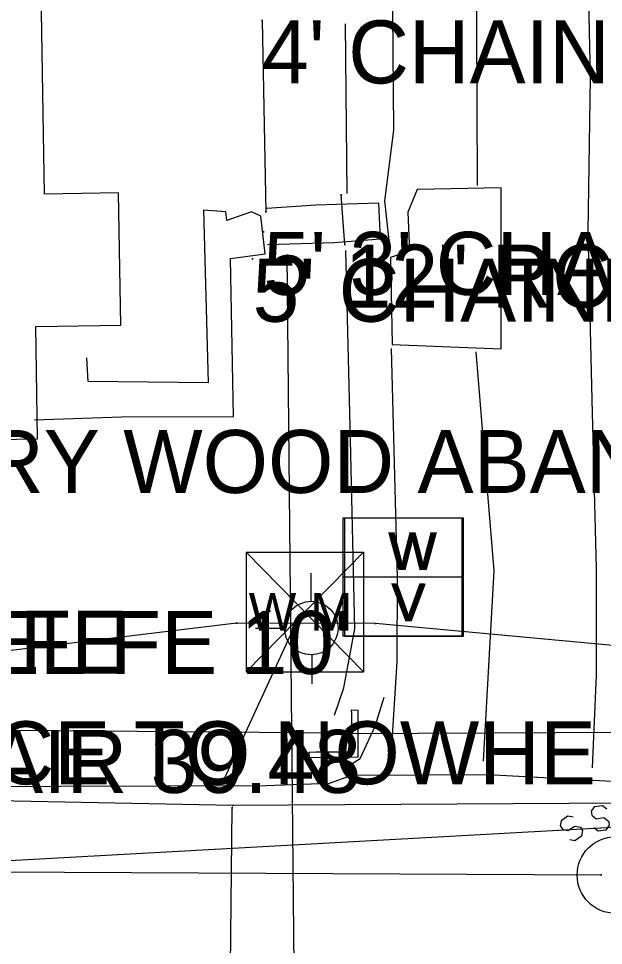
# Model space of a CAD drawing. Extents: x 1304270 to 1306561, y 1876019 to 1876752.
# Drawn here: x 1305299.9 to 1305346.4, y 1876408.6 to 1876482.3 of the extents above; entities that cross this region are included whole.
import ezdxf

# ---------------------------------------------------------------- set-up
doc = ezdxf.new("R2010")
doc.units = 0
for name, color, linetype in [('Default', 7, 'Continuous'), ('S_BUILDING', 7, 'Continuous'), ('S_CROSS_DRAIN', 7, 'Continuous'), ('S_DITCHLINE', 7, 'Continuous'), ('S_DRG_PT_SYM', 7, 'Continuous'), ('S_EDGE_CONCRETE', 7, 'Continuous'), ('S_EDGE_PAVEMENT', 7, 'Continuous'), ('S_FENCE', 7, 'Continuous'), ('S_FENCE_ANNOT', 7, 'Continuous'), ('S_FIBER_OPTIC_CABLE', 7, 'Continuous'), ('S_GAS_UTILITIES', 7, 'Continuous'), ('S_GATE_ANNOT', 7, 'Continuous'), ('S_HEADWALL', 7, 'Continuous'), ('S_MSC_PT_SYM', 7, 'Continuous'), ('S_PAVEMENT_CROWN', 7, 'Continuous'), ('S_SANITARY_SEWER', 7, 'Continuous'), ('S_SIDE_DRAIN', 7, 'Continuous'), ('S_SIDE_DRAIN_ANNOT', 7, 'Continuous'), ('S_SIDEWALK', 7, 'Continuous'), ('S_SURVEY_TEXT_ANNOT', 7, 'Continuous'), ('S_UTILITY_POLE', 7, 'Continuous'), ('S_UTL_PT_SYM', 7, 'Continuous'), ('S_WATER_UTILITIES', 7, 'Continuous')]:
    doc.layers.add(name, color=color, linetype=linetype)

msp = doc.modelspace()

# ---------------------------------------------------------------- linework, layer by layer
at = {"layer": 'Default'}
msp.add_line((1304873.941, 1876392.06), (1305473.534, 1876424.943), dxfattribs=at)
at = {"layer": 'S_BUILDING'}
msp.add_lwpolyline([(1305280.999, 1876496.939), (1305281.797, 1876448.543), (1305301.418, 1876448.867), (1305301.271, 1876457.78), (1305308.025, 1876457.891), (1305307.852, 1876468.402), (1305301.975, 1876468.305), (1305301.498, 1876497.277)], close=True, dxfattribs=at)
at = {"layer": 'S_CROSS_DRAIN'}
msp.add_line((1305350.386, 1876425.555), (1305326.154, 1876425.439), dxfattribs=at)
at = {"layer": 'S_DITCHLINE'}
for points in [[(1305326.03, 1876468.356), (1305325.896, 1876481.83)], [(1305325.015, 1876426.92), (1305325.765, 1876429.079), (1305326.635, 1876433.767), (1305326.286, 1876448.795), (1305325.938, 1876463.822)], [(1305247.208, 1876425.534), (1305267.671, 1876425.797), (1305283.635, 1876425.755), (1305299.6, 1876425.713), (1305312.565, 1876425.609), (1305325.53, 1876425.505)]]:
    msp.add_lwpolyline(points, dxfattribs=at)
at = {"layer": 'S_DRG_PT_SYM'}
for points in [[(1305325.565, 1876468.262), (1305325.565, 1876468.312), (1305325.565, 1876468.262), (1305325.515, 1876468.262), (1305325.565, 1876468.262), (1305325.565, 1876468.212), (1305325.565, 1876468.262), (1305325.615, 1876468.262)], [(1305325.836, 1876464.292), (1305325.836, 1876464.342), (1305325.836, 1876464.292), (1305325.786, 1876464.292), (1305325.836, 1876464.292), (1305325.836, 1876464.242), (1305325.836, 1876464.292), (1305325.886, 1876464.292)], [(1305326.154, 1876425.439), (1305326.154, 1876425.489), (1305326.154, 1876425.439), (1305326.104, 1876425.439), (1305326.154, 1876425.439), (1305326.154, 1876425.389), (1305326.154, 1876425.439), (1305326.204, 1876425.439)]]:
    msp.add_lwpolyline(points, dxfattribs=at)
at = {"layer": 'S_EDGE_CONCRETE'}
msp.add_lwpolyline([(1305329.608, 1876456.359), (1305338.28, 1876456.008), (1305338.273, 1876468.819), (1305331.607, 1876468.685), (1305330.863, 1876466.885), (1305330.981, 1876463.768), (1305329.472, 1876463.283)], close=True, dxfattribs=at)
at = {"layer": 'S_EDGE_PAVEMENT'}
for points in [[(1305329.455, 1876463.889), (1305329.018, 1876467.771), (1305329.753, 1876473.393), (1305329.675, 1876482.774), (1305329.429, 1876494.438), (1305330.166, 1876496.055), (1305329.938, 1876509.82)], [(1305345.542, 1876422.727), (1305345.856, 1876430.097), (1305345.86, 1876438.578), (1305345.525, 1876451.96), (1305345.191, 1876465.343), (1305345.392, 1876477.545), (1305345.052, 1876492.413), (1305344.713, 1876507.282)], [(1305329.473, 1876422.797), (1305330.003, 1876431.14), (1305330.022, 1876437.816), (1305329.567, 1876456.036)], [(1305325.882, 1876422.728), (1305327.054, 1876423.478), (1305328.271, 1876426.031), (1305328.967, 1876428.336)], [(1305129.363, 1876422.241), (1305153.047, 1876421.961), (1305176.731, 1876421.682), (1305192.781, 1876421.819), (1305208.83, 1876421.956), (1305222.689, 1876422.089), (1305236.664, 1876421.776), (1305244.109, 1876421.463), (1305257.339, 1876421.298), (1305270.568, 1876421.134), (1305295.068, 1876421.237), (1305319.567, 1876421.34), (1305324.623, 1876421.519), (1305326.394, 1876422.138), (1305337.227, 1876422.202), (1305349.547, 1876421.533), (1305351.837, 1876421.087), (1305367.555, 1876421.039), (1305383.273, 1876420.992)]]:
    msp.add_lwpolyline(points, dxfattribs=at)
at = {"layer": 'S_FENCE'}
msp.add_line((1305319.262, 1876482.101), (1305319.557, 1876466.887), dxfattribs=at)
msp.add_lwpolyline([(1305319.262, 1876482.101), (1305319.557, 1876466.887)], dxfattribs=at)
msp.add_lwpolyline([(1305319.262, 1876482.101), (1305319.557, 1876466.887)], dxfattribs=at)
at = {"layer": 'S_FIBER_OPTIC_CABLE'}
for p, q in [((1305317.236, 1876434.23), (1305297.346, 1876431.803)), ((1305328.281, 1876434.187), (1305317.236, 1876434.23)), ((1305347.146, 1876432.44), (1305328.281, 1876434.187))]:
    msp.add_line(p, q, dxfattribs=at)
at = {"layer": 'S_GAS_UTILITIES'}
msp.add_line((1305321.239, 1876463.459), (1305322.005, 1876385.242), dxfattribs=at)
at = {"layer": 'S_HEADWALL'}
msp.add_lwpolyline([(1305326.885, 1876427.325), (1305326.894, 1876427.104), (1305326.876, 1876423.577), (1305323.169, 1876423.523), (1305323.036, 1876423.486), (1305323.005, 1876423.99), (1305323.573, 1876424.004), (1305326.398, 1876424.002), (1305326.395, 1876427.036), (1305326.368, 1876427.348)], close=True, dxfattribs=at)
at = {"layer": 'S_MSC_PT_SYM'}
for points in [[(1305319.262, 1876482.101), (1305319.262, 1876482.151), (1305319.262, 1876482.101), (1305319.212, 1876482.101), (1305319.262, 1876482.101), (1305319.262, 1876482.051), (1305319.262, 1876482.101), (1305319.312, 1876482.101)], [(1305319.557, 1876466.887), (1305319.557, 1876466.937), (1305319.557, 1876466.887), (1305319.507, 1876466.887), (1305319.557, 1876466.887), (1305319.557, 1876466.837), (1305319.557, 1876466.887), (1305319.607, 1876466.887)], [(1305319.368, 1876465.305), (1305319.368, 1876465.355), (1305319.368, 1876465.305), (1305319.318, 1876465.305), (1305319.368, 1876465.305), (1305319.368, 1876465.255), (1305319.368, 1876465.305), (1305319.418, 1876465.305)], [(1305318.506, 1876463.169), (1305318.506, 1876463.219), (1305318.506, 1876463.169), (1305318.456, 1876463.169), (1305318.506, 1876463.169), (1305318.506, 1876463.119), (1305318.506, 1876463.169), (1305318.556, 1876463.169)], [(1305319.885, 1876435.182), (1305319.885, 1876435.232), (1305319.885, 1876435.182), (1305319.835, 1876435.182), (1305319.885, 1876435.182), (1305319.885, 1876435.132), (1305319.885, 1876435.182), (1305319.935, 1876435.182)]]:
    msp.add_lwpolyline(points, dxfattribs=at)
at = {"layer": 'S_PAVEMENT_CROWN'}
for points in [[(1305336.405, 1876469.001), (1305336.307, 1876488.339), (1305336.209, 1876507.677)], [(1305336.886, 1876423.262), (1305337.727, 1876438.394), (1305336.28, 1876455.776)]]:
    msp.add_lwpolyline(points, dxfattribs=at)
at = {"layer": 'S_SANITARY_SEWER'}
for p, q in [((1305343.042, 1876418.517), (1305342.964, 1876418.13)), ((1305343.584, 1876418.905), (1305343.042, 1876418.517)), ((1305344.011, 1876418.827), (1305343.584, 1876418.905)), ((1305342.964, 1876418.13), (1305343.158, 1876417.859)), ((1305343.158, 1876417.859), (1305343.584, 1876417.742)), ((1305343.584, 1876417.742), (1305344.127, 1876418.091)), ((1305344.127, 1876418.091), (1305344.592, 1876418.014)), ((1305344.592, 1876418.014), (1305344.747, 1876417.742)), ((1305344.747, 1876417.742), (1305344.669, 1876417.316)), ((1305344.127, 1876416.929), (1305343.739, 1876417.006)), ((1305344.669, 1876417.316), (1305344.127, 1876416.929)), ((1304983.663, 1876415.964), (1305346.234, 1876414.239))]:
    msp.add_line(p, q, dxfattribs=at)
msp.add_lwpolyline([(1305346.684, 1876419.447), (1305346.336, 1876419.719), (1305345.677, 1876419.641), (1305345.444, 1876419.292), (1305345.483, 1876418.982), (1305345.832, 1876418.672), (1305346.452, 1876418.789), (1305346.839, 1876418.479), (1305346.878, 1876418.169), (1305346.607, 1876417.781), (1305345.987, 1876417.704), (1305345.638, 1876417.975)], dxfattribs=at)
msp.add_circle((1305347.369, 1876414.214), 3.048, dxfattribs=at)
at = {"layer": 'S_SIDE_DRAIN'}
msp.add_line((1305325.836, 1876464.292), (1305325.565, 1876468.262), dxfattribs=at)
at = {"layer": 'S_SIDEWALK'}
for points in [[(1305301.168, 1876450.369), (1305308.091, 1876450.611), (1305316.982, 1876450.648), (1305316.766, 1876463.197), (1305319.523, 1876463.563), (1305319.171, 1876466.545), (1305318.438, 1876466.9), (1305316.469, 1876466.198), (1305316.385, 1876466.898), (1305314.621, 1876467.03), (1305314.969, 1876453.322), (1305305.43, 1876453.421), (1305305.338, 1876455.289)], [(1305319.692, 1876464.309), (1305324.992, 1876464.471), (1305328.682, 1876464.759), (1305328.56, 1876467.592), (1305323.538, 1876467.417), (1305319.652, 1876467.17)]]:
    msp.add_lwpolyline(points, dxfattribs=at)
at = {"layer": 'S_UTILITY_POLE'}
for p, q in [((1305323.174, 1876435.945), (1305323.174, 1876438.193)), ((1305321.082, 1876433.814), (1305318.757, 1876433.814)), ((1305323.252, 1876429.397), (1305323.252, 1876431.722))]:
    msp.add_line(p, q, dxfattribs=at)
msp.add_circle((1305323.177, 1876433.835), 2.128, dxfattribs=at)
at = {"layer": 'S_UTL_PT_SYM'}
for points in [[(1305321.239, 1876463.459), (1305321.239, 1876463.509), (1305321.239, 1876463.459), (1305321.189, 1876463.459), (1305321.239, 1876463.459), (1305321.239, 1876463.409), (1305321.239, 1876463.459), (1305321.289, 1876463.459)], [(1305317.236, 1876434.23), (1305317.236, 1876434.28), (1305317.236, 1876434.23), (1305317.186, 1876434.23), (1305317.236, 1876434.23), (1305317.236, 1876434.18), (1305317.236, 1876434.23), (1305317.286, 1876434.23)], [(1305321.961, 1876434.236), (1305321.961, 1876434.286), (1305321.961, 1876434.236), (1305321.91, 1876434.236), (1305321.961, 1876434.236), (1305321.961, 1876434.186), (1305321.961, 1876434.236), (1305322.011, 1876434.236)], [(1305328.281, 1876434.187), (1305328.281, 1876434.237), (1305328.281, 1876434.187), (1305328.231, 1876434.187), (1305328.281, 1876434.187), (1305328.281, 1876434.137), (1305328.281, 1876434.187), (1305328.331, 1876434.187)], [(1305316.117, 1876421.579), (1305316.117, 1876421.629), (1305316.117, 1876421.579), (1305316.067, 1876421.579), (1305316.117, 1876421.579), (1305316.117, 1876421.529), (1305316.117, 1876421.579), (1305316.167, 1876421.579)], [(1305316.892, 1876419.562), (1305316.892, 1876419.612), (1305316.892, 1876419.562), (1305316.842, 1876419.562), (1305316.892, 1876419.562), (1305316.892, 1876419.512), (1305316.892, 1876419.562), (1305316.942, 1876419.562)], [(1305316.936, 1876419.741), (1305316.936, 1876419.791), (1305316.936, 1876419.741), (1305316.886, 1876419.741), (1305316.936, 1876419.741), (1305316.936, 1876419.691), (1305316.936, 1876419.741), (1305316.986, 1876419.741)], [(1305346.234, 1876414.239), (1305346.234, 1876414.289), (1305346.234, 1876414.239), (1305346.184, 1876414.239), (1305346.234, 1876414.239), (1305346.234, 1876414.189), (1305346.234, 1876414.239), (1305346.284, 1876414.239)]]:
    msp.add_lwpolyline(points, dxfattribs=at)
at = {"layer": 'S_WATER_UTILITIES'}
for p, q in [((1305325.723, 1876442.603), (1305335.139, 1876442.603)), ((1305325.723, 1876433.187), (1305325.723, 1876442.603)), ((1305325.848, 1876442.592), (1305335.264, 1876442.592)), ((1305325.848, 1876433.176), (1305325.848, 1876442.592)), ((1305335.139, 1876442.603), (1305335.139, 1876433.187)), ((1305335.264, 1876442.592), (1305335.264, 1876433.176)), ((1305317.998, 1876439.863), (1305327.337, 1876439.863)), ((1305317.998, 1876439.863), (1305317.998, 1876430.369)), ((1305317.998, 1876439.863), (1305327.337, 1876430.369)), ((1305327.337, 1876439.863), (1305317.998, 1876430.369)), ((1305327.337, 1876439.863), (1305327.337, 1876430.369)), ((1305325.723, 1876437.914), (1305335.139, 1876437.914)), ((1305325.848, 1876437.903), (1305335.264, 1876437.903)), ((1305321.961, 1876434.236), (1305316.117, 1876421.579)), ((1305335.139, 1876433.187), (1305325.723, 1876433.187)), ((1305335.264, 1876433.176), (1305325.848, 1876433.176)), ((1305317.998, 1876430.369), (1305327.337, 1876430.369)), ((1305316.936, 1876419.741), (1305236.411, 1876421.32)), ((1305362.843, 1876419.995), (1305316.936, 1876419.741)), ((1305316.534, 1876386.063), (1305316.892, 1876419.562))]:
    msp.add_line(p, q, dxfattribs=at)

# ---------------------------------------------------------------- texts
at = {"layer": 'S_FENCE_ANNOT'}
for s, p in [("4' CHAINLINK GOOD", (1305319.262, 1876477.101)), ("5' CHAINLINK MTL POST", (1305318.506, 1876458.169)), ("3' WOODEN PRIVACY FE", (1305229.256, 1876430.208)), ("6' TALL CHINLIK PANEL FE 10'", (1305230.445, 1876430.19))]:
    msp.add_text(s, height=5, dxfattribs=at).set_placement(p)
at = {"layer": 'S_GATE_ANNOT'}
msp.add_text("5' 3' CHAINLINK MTL GT POOR", height=5, dxfattribs=at).set_placement((1305319.368, 1876460.305))
at = {"layer": 'S_SIDE_DRAIN_ANNOT'}
for s, p in [('12" RCP 25% FAIR DEL ABOVE SHOTS 4.21', (1305325.836, 1876459.292)), ('12" RCP 100% FAIR 39.48', (1305246.719, 1876420.744))]:
    msp.add_text(s, height=5, dxfattribs=at).set_placement(p)
at = {"layer": 'S_SURVEY_TEXT_ANNOT'}
for s, p in [('1 STRY WOOD ABANDON BU/HOME', (1305282.963, 1876444.567)), ('GRVL DW/ENTRANCE TO NOWHE', (1305237.356, 1876421.425))]:
    msp.add_text(s, height=5, dxfattribs=at).set_placement(p)
at = {"layer": 'S_WATER_UTILITIES'}
for s, p in [('W', (1305329.274, 1876438.446)), ('W', (1305329.399, 1876438.435)), ('V', (1305329.51, 1876434.383)), ('V', (1305329.635, 1876434.372)), ('W M', (1305318.203, 1876433.629))]:
    msp.add_text(s, height=3, rotation=360, dxfattribs=at).set_placement(p)

doc.saveas('drawing.dxf')
